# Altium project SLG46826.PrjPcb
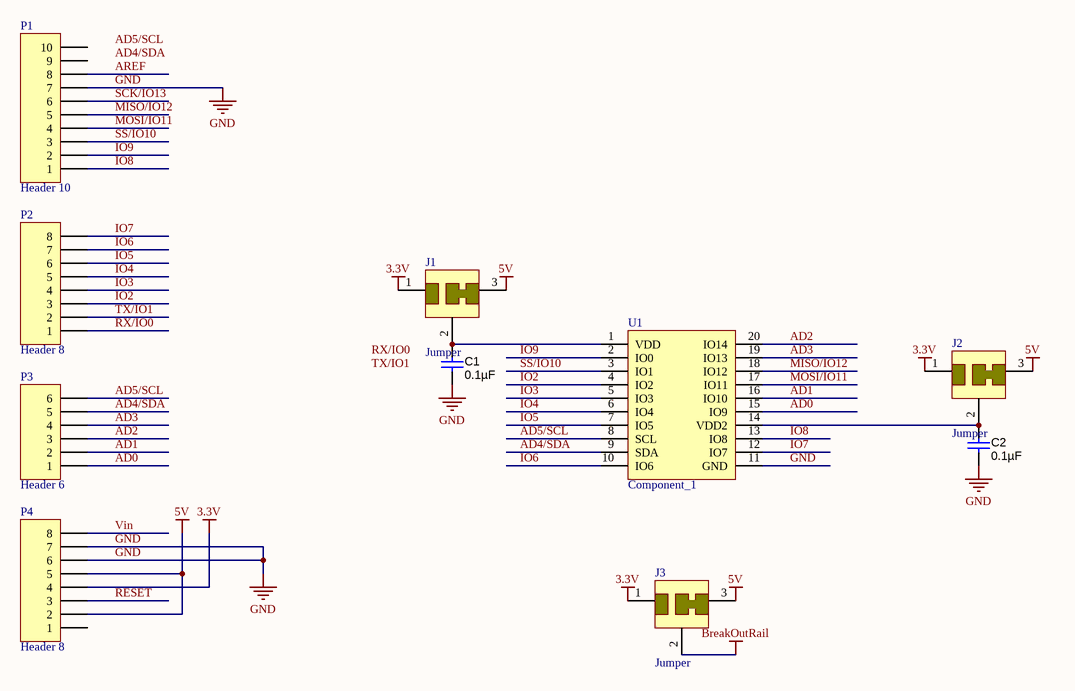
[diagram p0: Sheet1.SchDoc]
1 sheet, 10 parts. Net scope: global (net labels, ports and power ports of the same name join across sheets).
Board file: PCB1.PcbDoc

## Sheet Sheet1.SchDoc
size A

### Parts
C1  ValueDisplayed: 0.1µF  [0805_HV]  (hidden comment: C2012X5R1H104M085AA)
C2  ValueDisplayed: 0.1µF  [0805_HV]  (hidden comment: C2012X5R1H104M085AA)
J1  Jumper  [JUMPER]  (net tie, no BOM)
J2  Jumper  [JUMPER]  (net tie, no BOM)
J3  Jumper  [JUMPER]  (net tie, no BOM)
P1  Header 10  [HDR1X10]
P2  Header 8  [HDR1X8]
P3  Header 6  [HDR1X6]
P4  Header 8  [HDR1X8]
U1  Component_1  [STQFN]

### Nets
3.3V: J1.1 J2.1 J3.1 P4.4
5V: J1.3 J2.3 J3.3 P4.2 P4.5
BreakOutRail: J3.2
GND: C1.2 C2.2 P1.7 P4.6 P4.7 U1.11(GND)
AD0: P3.1 U1.15(IO9)
AD1: P3.2 U1.16(IO10)
AD2: P3.3 U1.20(IO14)
AD3: P3.4 U1.19(IO13)
AD4/SDA: P3.5 U1.9(SDA)
AD5/SCL: P3.6 U1.8(SCL)
AREF: P1.8
IO2: P2.3 U1.4(IO2)
IO3: P2.4 U1.5(IO3)
IO4: P2.5 U1.6(IO4)
IO5: P2.6 U1.7(IO5)
IO6: P2.7 U1.10(IO6)
IO7: P2.8 U1.12(IO7)
IO8: P1.1 U1.13(IO8)
IO9: P1.2 U1.2(IO0)
MISO/IO12: P1.5 U1.18(IO12)
MOSI/IO11: P1.4 U1.17(IO11)
RESET: P4.3
RX/IO0: P2.1
SCK/IO13: P1.6
SS/IO10: P1.3 U1.3(IO1)
TX/IO1: P2.2
Vin: P4.8
NetC1_1: C1.1 J1.2 U1.1(VDD)
NetC2_1: C2.1 J2.2 U1.14(VDD2)

Not connected (* = marked no-connect by the designer): P1 9 10; P4 1

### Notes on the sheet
- Labels drawn without touching a wire or pin: AD4/SDA, AD5/SCL, RX/IO0, TX/IO1

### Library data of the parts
C1 C2 = C2012X5R1H104M085AA: CAP, CERM, 0.1 µF, 50 V, +/- 20%, X5R, 0805; Manufacturer: TDK; Polarized: N; CompType: Capacitor; Value: 0.1uF; U/M: EA; Cap_F: 0.0000001; Tolerance_%: 20; ESR_ohm: 0.02619; Value1: 0.02619 ohm; VDC_V: 50; Value2: 50V; IRMS_A: 1.29514; TaMin_C: -55; TaMax_C: 85; Cap_Case: 0805; SizeArea_mm2: 2.5; SizeAreaWB_mm2: 6.75; SizeX_mm: 2; SizeY_mm: 1.25; SizeZ_mm: 1.45; AEC Category: Q200
P1 = Header 10: Header, 10-Pin
P2 P4 = Header 8: Header, 8-Pin
P3 = Header 6: Header, 6-Pin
